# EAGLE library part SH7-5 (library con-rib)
RIBBON CABLE CONNECTOR Flachstecker / Faston
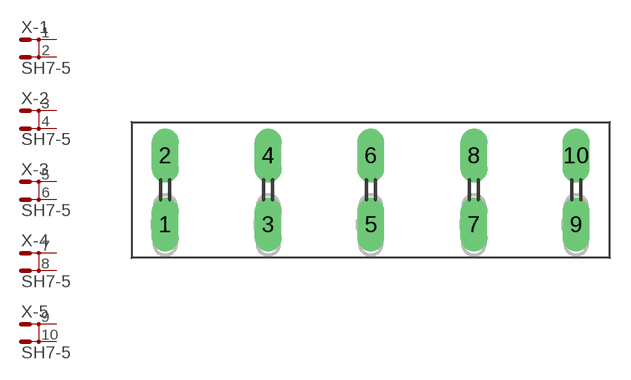
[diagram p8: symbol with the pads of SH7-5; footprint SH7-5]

Designator prefix X; gates -1=MD -2=MD -3=MD -4=MD -5=MD

## SH7-5  [SH7-5]
1  -1:1  pas
2  -1:2  pas
3  -2:1  pas
4  -2:2  pas
5  -3:1  pas
6  -3:2  pas
7  -4:1  pas
8  -4:2  pas
9  -5:1  pas
10  -5:2  pas

## Footprint SH7-5 (pad centres in mm)
RIBBON CABLE CONNECTOR Flachstecker / Faston
drill 1.321 long: 1 -15.011,-2.515; 2 -15.011,2.515; 3 -7.493,-2.515; 4 -7.493,2.515; 5 0,-2.515; 6 0,2.515; 7 7.518,-2.515; 8 7.518,2.515; 9 14.986,-2.515; 10 14.986,2.515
